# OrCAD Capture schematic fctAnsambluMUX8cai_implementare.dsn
size A
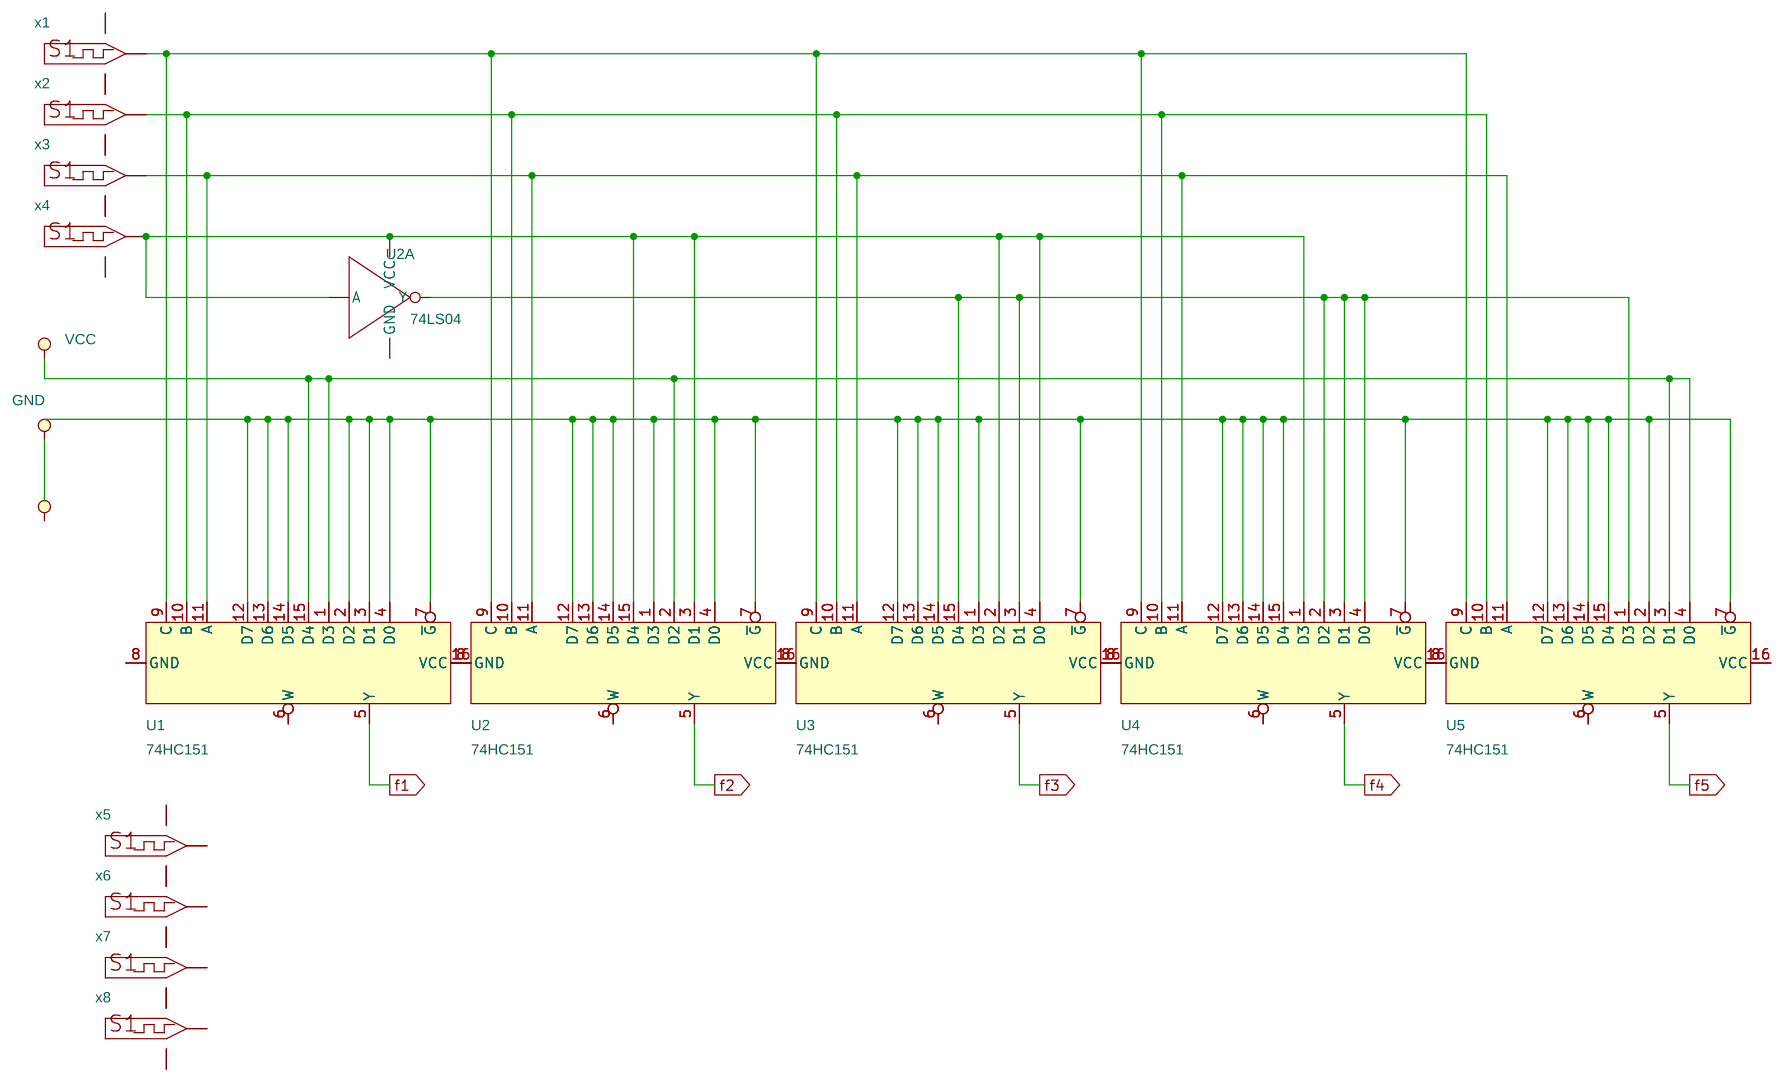
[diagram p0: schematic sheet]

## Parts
U1  74HC151  [DIP.100/16/W.300/L.900]
U2  74LS04  [DIP.100/14/W.300/L.800]  (section A)
U3  74HC151  [DIP.100/16/W.300/L.900]
U4  74HC151  [DIP.100/16/W.300/L.900]
U5  74HC151  [DIP.100/16/W.300/L.900]
x1  DigStim1
x2  DigStim1
x3  DigStim1
x4  DigStim1
x5  DigStim1
x6  DigStim1
x7  DigStim1
x8  DigStim1

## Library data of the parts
U1 U3-U5 = 74HC151
U2 = 74LS04
x1-x8 = DigStim1

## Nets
0: U1.1(D3) U1.2(D2) U1.3(D1) U1.4(D0) U1.7(~{G}) U1.8(GND) U1.12(D7) U1.13(D6) U1.14(D5) U1.15(D4) U1.16(VCC) U2.1(D3) U2.2(D2) U2.3(D1) U2.4(D0) U2.7(~{G}) U2.8(GND) U2.12(D7) U2.13(D6) U2.14(D5) U2.15(D4) U2.16(VCC) U3.1(D3) U3.2(D2) U3.3(D1) U3.4(D0) U3.7(~{G}) U3.8(GND) U3.12(D7) U3.13(D6) U3.14(D5) U3.15(D4) U3.16(VCC) U4.1(D3) U4.2(D2) U4.3(D1) U4.4(D0) U4.7(~{G}) U4.8(GND) U4.12(D7) U4.13(D6) U4.14(D5) U4.15(D4) U4.16(VCC) U5.1(D3) U5.2(D2) U5.3(D1) U5.4(D0) U5.7(~{G}) U5.8(GND) U5.12(D7) U5.13(D6) U5.14(D5) U5.15(D4) U5.16(VCC) x1.2(VCC) x1.3(GND) x2.2(VCC) x2.3(GND) x3.2(VCC) x3.3(GND) x4.2(VCC) x4.3(GND) x4.OUT x5.2(VCC) x5.3(GND) x6.2(VCC) x6.3(GND) x7.2(VCC) x7.3(GND) x8.2(VCC) x8.3(GND)
f1: U1.5(Y)
f2: U2.5(Y)
f3: U3.5(Y)
f4: U4.5(Y)
f5: U5.5(Y)
N26408: U1.11(A) U2.11(A) U3.11(A) U4.11(A) U5.11(A) x3.OUT
N26418: U1.10(B) U2.10(B) U3.10(B) U4.10(B) U5.10(B) x2.OUT
N26422: U1.9(C) U2.9(C) U3.9(C) U4.9(C) U5.9(C) x1.OUT

Not connected (* = marked no-connect by the designer): U1 6(W); U2 6(W); U3 6(W); U4 6(W); U5 6(W); x5 OUT; x6 OUT; x7 OUT; x8 OUT
